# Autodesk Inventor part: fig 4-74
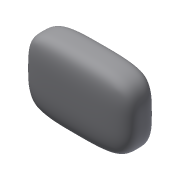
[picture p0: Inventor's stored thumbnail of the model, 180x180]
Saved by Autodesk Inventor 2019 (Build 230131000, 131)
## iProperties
Created: 2012-07
Part Number: fig 4-74
Material: Generic
Document SubType Name: Modeling
Designer: CADCIM
Density: 1 g/cm^3
Appearance: Default
Author: CADCIM
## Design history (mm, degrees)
feature "Form1"
body "Solid1"
body "Solid2"
